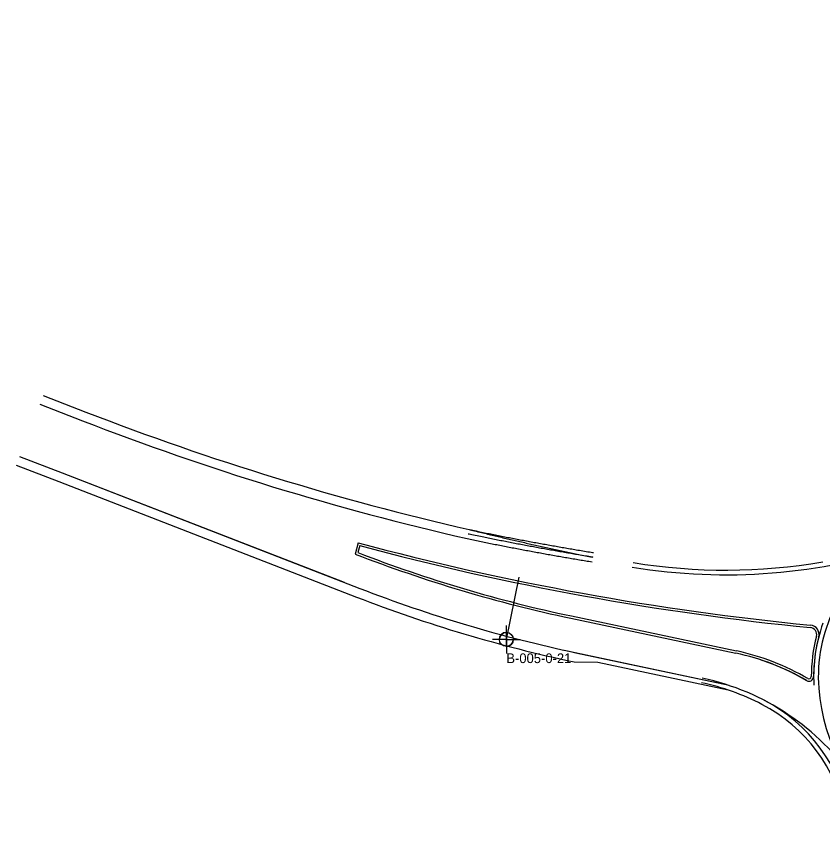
# Model space of a CAD drawing. Extents: x 2047259 to 2048296, y 456488 to 457733.
# Drawn here: x 2047259.3 to 2047605, y 456962.9 to 457310.5 of the extents above; entities that cross this region are included whole.
import ezdxf

# ---------------------------------------------------------------- set-up
doc = ezdxf.new("R2010")
doc.units = 0
for name, color, linetype in [('Default', 7, 'Continuous'), ('DT_X_Break_Line', 7, 'Continuous'), ('DT_X_Contour_Major', 7, 'Continuous'), ('DT_X_Contour_Minor', 7, 'Continuous'), ('DT_X_Contour_Text', 7, 'Continuous'), ('DT_X_Spot_Elev', 7, 'Continuous')]:
    doc.layers.add(name, color=color, linetype=linetype)

msp = doc.modelspace()

# ---------------------------------------------------------------- linework, layer by layer
at = {"layer": 'Default'}
msp.add_line((2047469.38, 457043.26), (2047474.9, 457069.88), dxfattribs=at)
at = {"layer": 'DT_X_Break_Line'}
for p, q in [((2047469.38, 457043.26), (2047469.38, 457049.26)), ((2047469.38, 457046.26), (2047469.38, 457043.26)), ((2047469.38, 457043.26), (2047463.38, 457043.26)), ((2047469.38, 457043.26), (2047466.38, 457043.26)), ((2047469.38, 457043.26), (2047469.38, 457037.26)), ((2047469.38, 457043.26), (2047475.38, 457043.26)), ((2047469.38, 457040.26), (2047469.38, 457043.26)), ((2047469.38, 457043.26), (2047472.38, 457043.26))]:
    msp.add_line(p, q, dxfattribs=at)
msp.add_circle((2047469.38, 457043.26), 3, dxfattribs=at)
for start, end in [(90, 180), (270, 360)]:
    msp.add_arc((2047469.38, 457043.26), 3, start, end, dxfattribs=at)
at = {"layer": 'DT_X_Contour_Major'}
for p, q in [((2047269.39, 457144.13), (2047287.66, 457137.04)), ((2047260.71, 457121.76), (2047278.98, 457114.67)), ((2047278.98, 457114.67), (2047399.84, 457067.77)), ((2047278.98, 457114.67), (2047406.55, 457065.16)), ((2047494.18, 457038.63), (2047564.92, 457023.64)), ((2047499.24, 457037.56), (2047564.92, 457023.64))]:
    msp.add_line(p, q, dxfattribs=at)
for centre, radius, start, end in [((2047717.44, 458244.57), 1188, 248.79098, 257.11818), ((2047563.52, 457320.97), 250, 260.7593, 288.3105), ((2047563.52, 457320.97), 250, 260.7593, 288.3105), ((2047623.61, 457624.52), 600, 248.79098, 258.03635), ((2047531.63, 456923.9), 105, 34.2773, 78.0363), ((2047531.63, 456923.9), 105, 34.2773, 78.0363), ((2047547.72, 456954.99), 70, 10.3817, 62.6377)]:
    msp.add_arc(centre, radius, start, end, dxfattribs=at)
msp.add_open_spline([(2047452.59, 457086.47), (2047453.48, 457086.29), (2047455.26, 457085.92), (2047457.92, 457085.37), (2047460.59, 457084.83), (2047463.26, 457084.29), (2047465.93, 457083.76), (2047468.6, 457083.23), (2047471.27, 457082.72), (2047473.95, 457082.2), (2047476.62, 457081.7), (2047479.3, 457081.2), (2047481.97, 457080.7), (2047484.65, 457080.22), (2047487.33, 457079.74), (2047490.01, 457079.26), (2047492.69, 457078.79), (2047495.37, 457078.33), (2047498.05, 457077.87), (2047500.74, 457077.42), (2047503.42, 457076.98), (2047505.21, 457076.69), (2047506.11, 457076.54)], degree=3, dxfattribs=at)
msp.add_open_spline([(2047452.59, 457086.47), (2047453.48, 457086.29), (2047455.26, 457085.92), (2047457.92, 457085.37), (2047460.59, 457084.83), (2047463.26, 457084.29), (2047465.93, 457083.76), (2047468.6, 457083.23), (2047471.27, 457082.72), (2047473.95, 457082.2), (2047476.62, 457081.7), (2047479.3, 457081.2), (2047481.97, 457080.7), (2047484.65, 457080.22), (2047487.33, 457079.74), (2047490.01, 457079.26), (2047492.69, 457078.79), (2047495.37, 457078.33), (2047498.05, 457077.87), (2047500.74, 457077.42), (2047503.42, 457076.98), (2047505.21, 457076.69), (2047506.11, 457076.54)], degree=3, dxfattribs=at)
at = {"layer": 'DT_X_Contour_Minor'}
for p, q in [((2047270.84, 457147.86), (2047289.11, 457140.77)), ((2047259.26, 457118.03), (2047277.53, 457110.94)), ((2047277.53, 457110.94), (2047405.1, 457061.43))]:
    msp.add_line(p, q, dxfattribs=at)
for centre, radius, start, end in [((2049528.91, 457641.59), 1926, 181.11347, 190.26352), ((2047717.44, 458244.57), 1184, 248.79098, 257.11818), ((2047623.61, 457624.52), 604, 248.79098, 258.03635)]:
    msp.add_arc(centre, radius, start, end, dxfattribs=at)
msp.add_open_spline([(2047453.41, 457090.39), (2047453.91, 457090.28), (2047455.66, 457089.92), (2047458.83, 457089.27), (2047461.35, 457088.75), (2047464.05, 457088.21), (2047466.7, 457087.68), (2047469.36, 457087.16), (2047472.03, 457086.64), (2047474.69, 457086.13), (2047477.36, 457085.63), (2047480.02, 457085.13), (2047482.69, 457084.64), (2047485.36, 457084.15), (2047488.03, 457083.67), (2047490.7, 457083.2), (2047493.37, 457082.73), (2047496.04, 457082.27), (2047498.75, 457081.81), (2047501.28, 457081.39), (2047504.48, 457080.86), (2047506.24, 457080.57), (2047506.75, 457080.49)], degree=3, dxfattribs=at)
at = {"layer": 'DT_X_Contour_Text'}
for centre, radius, start, end in [((2047669.12, 457027.27), 66, 153.7154, 184.2256), ((2047684.08, 457028.38), 81, 184.2256, 233.9294)]:
    msp.add_arc(centre, radius, start, end, dxfattribs=at)
at = {"layer": 'DT_X_Spot_Elev'}
for p, q in [((2047405.84, 457084.7), (2047404.54, 457079.88)), ((2047406.54, 457083.48), (2047405.74, 457080.49)), ((2047497.08, 457052.32), (2047567.82, 457037.33)), ((2047497.08, 457052.32), (2047567.82, 457037.33)), ((2047497.08, 457052.32), (2047567.82, 457037.33)), ((2047497.28, 457053.3), (2047568.03, 457038.31)), ((2047498.41, 457033.64), (2047508.6, 457033.53)), ((2047508.6, 457033.53), (2047564.51, 457021.68))]:
    msp.add_line(p, q, dxfattribs=at)
for centre, radius, start, end in [((2047717.44, 458244.57), 1201, 254.96223, 264.37974), ((2047717.44, 458244.57), 1201, 254.96223, 264.37974), ((2047717.44, 458244.57), 1201, 254.96223, 264.37974), ((2047717.44, 458244.57), 1202, 255.00989, 264.37974), ((2047621.24, 457638.31), 599, 248.79098, 258.03635), ((2047621.24, 457638.31), 599, 248.79098, 258.03635), ((2047621.24, 457638.31), 599, 248.79098, 258.03635), ((2047621.24, 457638.31), 598, 248.87698, 258.03635), ((2047563.52, 457320.97), 248, 260.7593, 279.6381), ((2047599.43, 457045.37), 3, 345.4453, 84.3797), ((2047599.43, 457045.37), 4, 345.4453, 84.3797), ((2047599.43, 457045.37), 4, 345.4453, 84.3797), ((2047669.12, 457027.27), 68, 160.2692, 183.0742), ((2047669.12, 457027.27), 69, 165.4453, 179.9796), ((2047669.12, 457027.27), 68, 165.4453, 179.9796), ((2047669.12, 457027.27), 68, 165.4453, 179.9796), ((2047546.89, 456938.53), 101, 59.6504, 78.0363), ((2047546.89, 456938.53), 101, 59.5257, 78.0363), ((2047546.89, 456938.53), 101, 59.5257, 78.0363), ((2047546.89, 456938.53), 102, 59.5257, 78.0363), ((2047599.12, 457027.3), 2, 239.5257, 359.9796), ((2047599.12, 457027.3), 2, 239.5257, 359.9796), ((2047599.12, 457027.3), 1, 239.5257, 359.9796), ((2047531.63, 456923.9), 103, 62.6377, 78.0363), ((2047547.72, 456954.99), 68, 10.3817, 62.6377)]:
    msp.add_arc(centre, radius, start, end, dxfattribs=at)
for points in [[(2047453.41, 457090.39), (2047453.91, 457090.27), (2047455.64, 457089.84), (2047458.79, 457089.07), (2047461.29, 457088.46), (2047463.97, 457087.82), (2047466.6, 457087.19), (2047469.25, 457086.57), (2047471.89, 457085.96), (2047474.54, 457085.35), (2047477.19, 457084.75), (2047479.84, 457084.15), (2047482.49, 457083.56), (2047485.14, 457082.97), (2047487.8, 457082.39), (2047490.46, 457081.82), (2047493.12, 457081.25), (2047495.77, 457080.7), (2047498.46, 457080.13), (2047500.99, 457079.61), (2047504.17, 457078.97), (2047505.92, 457078.62), (2047506.43, 457078.51)], [(2047506.43, 457078.51), (2047505.92, 457078.6), (2047504.16, 457078.88), (2047500.95, 457079.41), (2047498.41, 457079.84), (2047495.7, 457080.3), (2047493.03, 457080.76), (2047490.35, 457081.23), (2047487.68, 457081.71), (2047485, 457082.19), (2047482.33, 457082.67), (2047479.66, 457083.17), (2047476.99, 457083.66), (2047474.32, 457084.17), (2047471.65, 457084.68), (2047468.98, 457085.2), (2047466.31, 457085.72), (2047463.66, 457086.25), (2047460.96, 457086.79), (2047458.43, 457087.31), (2047455.25, 457087.96), (2047453.5, 457088.33), (2047453, 457088.43)]]:
    msp.add_open_spline(points, degree=3, dxfattribs=at)

# ---------------------------------------------------------------- texts
at = {"layer": 'Default'}
msp.add_text('B-005-0-21', height=4.167, dxfattribs=at).set_placement((2047469.38, 457033.1))

doc.saveas('drawing.dxf')
